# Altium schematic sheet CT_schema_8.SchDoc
size 287 x 160 mm
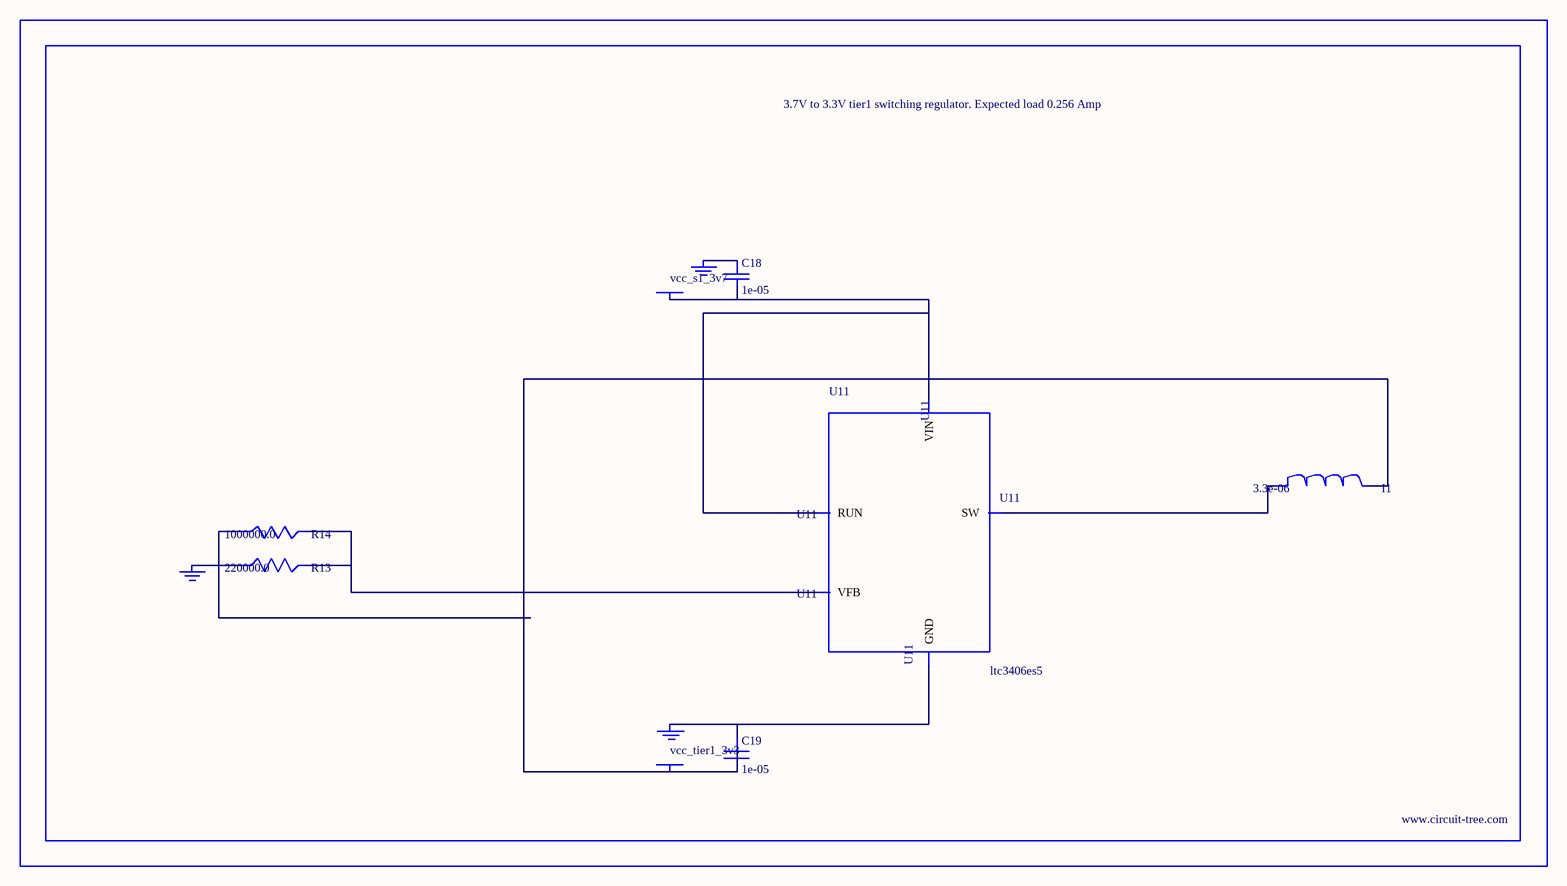
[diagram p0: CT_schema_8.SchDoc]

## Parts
BORDER7  (no value)
C18  1e-05  [C0805]
C19  1e-05  [C0805]
GND_INSTANCE_7_0  (no value)
GND_INSTANCE_7_1  (no value)
GND_INSTANCE_7_2  (no value)
I1  3.3e-06  [L0806]
POWER_INSTANCE_7_0  vcc_tier1_3v3
POWER_INSTANCE_7_1  vcc_s1_3v7
R13  220000.0  [R0603]
R14  1000000.0  [R0603]
U11  ltc3406es5  [TSOT-23-5]

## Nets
NetC18_1: C18.1 GND_INSTANCE_7_1.0(GND)
NetC18_2: C18.2 POWER_INSTANCE_7_1.0(PWR) U11.1(RUN) U11.4(VIN)
NetC19_1: C19.1 GND_INSTANCE_7_0.0(GND) U11.2(GND)
NetC19_2: C19.2 I1.2 POWER_INSTANCE_7_0.0(PWR) R14.1
NetGND_INSTANCE_7_2_0: GND_INSTANCE_7_2.0(GND) R13.1
NetI1_1: I1.1 U11.3(SW)
NetR13_2: R13.2 R14.2 U11.5(VFB)

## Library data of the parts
BORDER7 = BORDER_PAGE7
C18 C19 = C0805C106K8RACTU
GND_INSTANCE_7_0-GND_INSTANCE_7_2 = GND
I1 = L0806C3R3MDWIT
POWER_INSTANCE_7_0 POWER_INSTANCE_7_1 = PWR
R13 = RC0603JR-07220KL
R14 = RC0603JR-071ML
